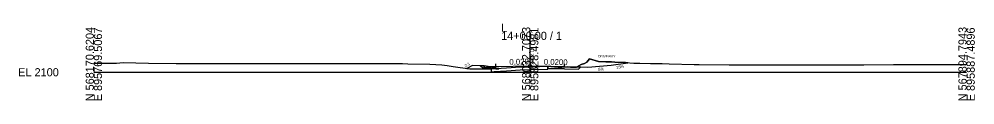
# Model space of a CAD drawing. Extents: x -26 to 1603, y -10 to 13527.
# Drawn here: x -25.7 to 302.8, y 1490.3 to 1516.7 of the extents above; entities that cross this region are included whole.
import ezdxf

# ---------------------------------------------------------------- set-up
doc = ezdxf.new("R2010")
doc.units = 0
for name, color, linetype in [('Default', 7, 'Continuous'), ('Exist XS Center Line Elevation Label', 7, 'Continuous'), ('Exist XS Ground Line', 7, 'Continuous'), ('Old_Level_61', 7, 'Continuous'), ('Old_Level_63', 7, 'Continuous'), ('Prop XS Ditch Slope Text', 7, 'Continuous'), ('Prop XS Ditch Standard Text', 7, 'Continuous'), ('Prop XS Earthwork Shape', 7, 'Continuous'), ('Prop XS EOT Tick Mark', 7, 'Continuous'), ('Prop XS Finish Grade', 7, 'Continuous'), ('Prop XS Finish Grade Earthwork', 7, 'Continuous'), ('Prop XS Finish Grade Paved Shoulder', 7, 'Continuous'), ('Prop XS Finish Grade Pavement', 7, 'Continuous'), ('Prop XS Subgrade Earthwork', 7, 'Continuous'), ('Prop XSC Text', 7, 'Continuous'), ('Typical Curb CELL', 7, 'Continuous')]:
    doc.layers.add(name, color=color, linetype=linetype)

msp = doc.modelspace()

# ---------------------------------------------------------------- linework, layer by layer
at = {"layer": 'Exist XS Ground Line'}
for p, q in [((0, 1503.13), (5.22, 1503.15)), ((5.22, 1503.15), (7.79, 1503.15)), ((7.79, 1503.15), (10.02, 1503.3)), ((10.02, 1503.3), (18.81, 1503.15)), ((18.81, 1503.15), (28.31, 1503.01)), ((28.31, 1503.01), (29.99, 1503.01)), ((29.99, 1503.01), (33.53, 1503)), ((33.53, 1503), (42.94, 1502.99)), ((42.94, 1502.99), (55.35, 1502.98)), ((55.35, 1502.98), (55.86, 1502.98)), ((55.86, 1502.98), (56.74, 1502.99)), ((56.74, 1502.99), (58.95, 1503)), ((58.95, 1503), (68.24, 1503.06)), ((68.24, 1503.06), (69.74, 1503.06)), ((69.74, 1503.06), (76.49, 1503)), ((76.49, 1503), (78.47, 1503)), ((78.47, 1503), (92.05, 1503.06)), ((92.05, 1503.06), (94.64, 1503.04)), ((94.64, 1503.04), (97.81, 1503.04)), ((97.81, 1503.04), (106.12, 1502.97)), ((106.12, 1502.97), (107.94, 1502.9)), ((107.94, 1502.9), (115.47, 1502.82)), ((115.47, 1502.82), (119.56, 1502.55)), ((119.56, 1502.55), (121.46, 1502.32)), ((121.46, 1502.32), (123.54, 1501.98)), ((123.54, 1501.98), (129.29, 1501.17)), ((136.4, 1501.17), (141.8, 1501.47)), ((141.8, 1501.47), (146.53, 1501.81)), ((146.53, 1501.81), (150, 1501.91)), ((150, 1501.91), (150.33, 1501.92)), ((150.33, 1501.92), (156.01, 1502.05)), ((156.01, 1502.05), (157.06, 1501.93)), ((157.06, 1501.93), (159.61, 1501.8)), ((159.61, 1501.8), (160.81, 1501.79)), ((160.81, 1501.79), (162.95, 1501.88)), ((162.95, 1501.88), (163.87, 1501.71)), ((163.87, 1501.71), (165.9, 1501.76)), ((165.9, 1501.76), (167.45, 1502.7)), ((167.45, 1502.7), (168.69, 1502.97)), ((168.69, 1502.97), (169.46, 1503.46)), ((169.46, 1503.46), (170.4, 1504.65)), ((170.4, 1504.65), (173.44, 1503.74)), ((173.44, 1503.74), (175.93, 1503.53)), ((175.93, 1503.53), (177.94, 1503.53)), ((177.94, 1503.53), (179.03, 1503.52)), ((179.03, 1503.52), (182.72, 1503.33)), ((182.72, 1503.33), (185.65, 1503.17)), ((185.65, 1503.17), (187.65, 1503.12)), ((187.65, 1503.12), (191.36, 1503)), ((191.36, 1503), (195.3, 1502.97)), ((195.3, 1502.97), (197.7, 1502.92)), ((197.7, 1502.92), (206.39, 1502.67)), ((206.39, 1502.67), (208.01, 1502.67)), ((208.01, 1502.67), (218.34, 1502.6)), ((218.34, 1502.6), (221.49, 1502.6)), ((221.49, 1502.6), (236.26, 1502.55)), ((236.26, 1502.55), (244.93, 1502.52)), ((244.93, 1502.52), (246.38, 1502.52)), ((246.38, 1502.52), (247.51, 1502.52)), ((247.51, 1502.52), (264.67, 1502.52)), ((264.67, 1502.52), (274.9, 1502.65)), ((274.9, 1502.65), (277.44, 1502.69)), ((277.44, 1502.69), (281.52, 1502.68)), ((281.52, 1502.68), (294.15, 1502.64)), ((294.15, 1502.64), (300, 1502.67)), ((129.29, 1501.17), (131.96, 1501.17)), ((131.96, 1501.17), (136.4, 1501.17))]:
    msp.add_line(p, q, dxfattribs=at)
at = {"layer": 'Old_Level_61'}
for p, q in [((156.05, 1501.05), (156.05, 1502.05)), ((136.54, 1501.18), (136.54, 1500.18)), ((136.54, 1500.18), (137.55, 1500.23)), ((137.55, 1500.23), (141.8, 1500.47)), ((141.8, 1500.47), (146.53, 1500.81)), ((146.53, 1500.81), (150, 1500.91)), ((150, 1500.91), (150.33, 1500.92)), ((150.33, 1500.92), (156.01, 1501.05)), ((156.01, 1501.05), (156.05, 1501.05))]:
    msp.add_line(p, q, dxfattribs=at)
at = {"layer": 'Old_Level_63'}
for p, q in [((150, 1500), (150, 1513.95)), ((0, 1500), (150, 1500)), ((150, 1500), (300, 1500))]:
    msp.add_line(p, q, dxfattribs=at)
at = {"layer": 'Prop XS Earthwork Shape'}
for points in [[(133.7, 1501.36), (132.83, 1502.23), (130.2, 1502.28), (128.26, 1501.31), (129.29, 1501.17), (131.96, 1501.17), (136.4, 1501.17), (138.2, 1501.27), (138.2, 1501.37), (134.2, 1501.37)], [(161.8, 1501.16), (166.63, 1501.07), (167.41, 1501.84), (169.8, 1501.79), (177.8, 1502.43), (183.49, 1503.29), (182.72, 1503.33), (179.03, 1503.52), (177.94, 1503.53), (175.93, 1503.53), (173.44, 1503.74), (170.4, 1504.65), (169.46, 1503.46), (168.69, 1502.97), (167.45, 1502.7), (165.9, 1501.76), (163.87, 1501.71), (162.95, 1501.88), (160.81, 1501.79), (159.61, 1501.8), (157.06, 1501.93), (156.05, 1502.05), (156.05, 1501.28)], [(138.2, 1501.16), (139.2, 1501.18), (139.2, 1501.32), (138.2, 1501.27)]]:
    msp.add_lwpolyline(points, close=True, dxfattribs=at)
at = {"layer": 'Prop XS EOT Tick Mark'}
for p, q in [((138.2, 1501.95), (138.2, 1502.95)), ((161.8, 1501.95), (161.8, 1502.95))]:
    msp.add_line(p, q, dxfattribs=at)
at = {"layer": 'Prop XS Finish Grade'}
for p, q in [((134.2, 1502.2), (132.83, 1502.23)), ((165.82, 1501.87), (167.41, 1501.84))]:
    msp.add_line(p, q, dxfattribs=at)
at = {"layer": 'Prop XS Finish Grade Earthwork'}
for p, q in [((130.2, 1502.28), (128.26, 1501.31)), ((132.83, 1502.23), (130.2, 1502.28)), ((167.41, 1501.84), (169.8, 1501.79)), ((169.8, 1501.79), (177.8, 1502.43)), ((177.8, 1502.43), (183.49, 1503.29))]:
    msp.add_line(p, q, dxfattribs=at)
at = {"layer": 'Prop XS Finish Grade Paved Shoulder'}
msp.add_line((161.8, 1501.95), (165.82, 1501.87), dxfattribs=at)
at = {"layer": 'Prop XS Finish Grade Pavement'}
for p, q in [((138.2, 1501.95), (150, 1502.19)), ((150, 1502.19), (161.8, 1501.95))]:
    msp.add_line(p, q, dxfattribs=at)
at = {"layer": 'Prop XS Subgrade Earthwork'}
for p, q in [((133.7, 1501.36), (132.83, 1502.23)), ((156.05, 1501.28), (156.05, 1502.05)), ((166.63, 1501.07), (167.41, 1501.84)), ((133.7, 1501.36), (134.2, 1501.37)), ((134.2, 1501.37), (138.2, 1501.37)), ((138.2, 1501.16), (138.2, 1501.37)), ((138.2, 1501.16), (139.2, 1501.18)), ((139.2, 1501.18), (139.2, 1501.32)), ((161.8, 1501.16), (156.05, 1501.28)), ((161.8, 1501.16), (166.63, 1501.07))]:
    msp.add_line(p, q, dxfattribs=at)
at = {"layer": 'Typical Curb CELL'}
for p, q in [((134.2, 1501.37), (134.2, 1502.2)), ((136.2, 1501.87), (134.2, 1502.2)), ((134.24, 1501.83), (134.39, 1501.87)), ((134.37, 1501.78), (134.24, 1501.83)), ((134.39, 1501.87), (134.37, 1501.78)), ((134.91, 1501.74), (134.8, 1501.67)), ((134.8, 1501.67), (134.97, 1501.63)), ((134.97, 1501.63), (134.91, 1501.74)), ((135.65, 1501.8), (135.61, 1501.69)), ((135.61, 1501.69), (135.73, 1501.68)), ((135.73, 1501.68), (135.65, 1501.8)), ((136.16, 1501.74), (136.05, 1501.67)), ((136.05, 1501.67), (136.22, 1501.63)), ((136.22, 1501.63), (136.16, 1501.74)), ((138.2, 1501.95), (136.2, 1501.87)), ((136.9, 1501.8), (136.86, 1501.69)), ((136.86, 1501.69), (136.98, 1501.68)), ((136.98, 1501.68), (136.9, 1501.8)), ((137.61, 1501.6), (137.51, 1501.52)), ((137.51, 1501.52), (137.67, 1501.48)), ((137.67, 1501.48), (137.61, 1501.6)), ((137.94, 1501.84), (137.91, 1501.73)), ((137.91, 1501.73), (138.03, 1501.72)), ((138.03, 1501.72), (137.94, 1501.84)), ((138.2, 1501.37), (138.2, 1501.95)), ((134.2, 1501.37), (138.2, 1501.37))]:
    msp.add_line(p, q, dxfattribs=at)
for centre in [(134.27, 1501.91), (134.36, 1501.64), (134.38, 1502.08), (134.45, 1501.53), (134.48, 1501.69), (134.58, 1502.06), (134.74, 1501.72), (134.76, 1501.67), (134.93, 1501.58), (134.95, 1501.98), (134.96, 1501.68), (135.15, 1501.46), (135.16, 1501.64), (135.2, 1501.76), (135.31, 1501.92), (135.33, 1501.73), (135.36, 1501.6), (135.42, 1501.64), (135.47, 1501.51), (135.61, 1501.64), (135.73, 1501.69), (135.77, 1501.83), (135.83, 1501.68), (135.83, 1501.48), (135.92, 1501.63), (135.98, 1501.78), (135.99, 1501.72), (136.01, 1501.67), (136.18, 1501.57), (136.21, 1501.68), (136.29, 1501.49), (136.41, 1501.64), (136.45, 1501.76), (136.5, 1501.73), (136.52, 1501.45), (136.58, 1501.73), (136.61, 1501.6), (136.67, 1501.64), (136.73, 1501.82), (136.84, 1501.46), (137.09, 1501.89), (137.13, 1501.77), (137.33, 1501.54), (137.48, 1501.81), (137.7, 1501.82), (137.77, 1501.59), (137.94, 1501.45), (138.06, 1501.61), (138.1, 1501.85)]:
    msp.add_circle(centre, 0.00802, dxfattribs=at)

# ---------------------------------------------------------------- texts
at = {"layer": 'Default'}
for rotation, p in [(1.1458, (142.84, 1502.55)), (358.8542, (154.64, 1502.6))]:
    msp.add_text('0.0200', height=2, rotation=rotation, dxfattribs=at).set_placement(p)
at = {"layer": 'Exist XS Center Line Elevation Label'}
msp.add_text('2101.91', height=1, rotation=90, dxfattribs=at).set_placement((150.5, 1494.95))
at = {"layer": 'Old_Level_63'}
for s, p in [('N 568170.6204', (0, 1490)), ('E 895769.5067', (2.8, 1490)), ('N 568032.7073', (150, 1490)), ('E 895828.4981', (152.8, 1490)), ('N 567894.7943', (300, 1490)), ('E 895887.4896', (302.8, 1490))]:
    msp.add_text(s, height=2.8, rotation=90, dxfattribs=at).set_placement(p)
for s, p in [('L', (140, 1513.95)), ('14+00.00 / 1', (140, 1511.15)), ('EL 2100', (-26, 1498.6))]:
    msp.add_text(s, height=2.8, dxfattribs=at).set_placement(p)
at = {"layer": 'Prop XS Ditch Slope Text'}
msp.add_text('2:1', height=1, rotation=32.2598, dxfattribs=at).set_placement((127.78, 1501.62))
at = {"layer": 'Prop XS Ditch Standard Text'}
msp.add_text('DRIVEWAY', height=0.8, dxfattribs=at).set_placement((173.34, 1505.1))
for s, rotation, p in [('8%', 4.5739, (173.39, 1500.5)), ('15%', 9.8514, (179.64, 1501.13))]:
    msp.add_text(s, height=1, rotation=rotation, dxfattribs=at).set_placement(p)
at = {"layer": 'Prop XSC Text'}
msp.add_text(' 2102.19', height=1.2, rotation=90, dxfattribs=at).set_placement((151.2, 1502.19))

doc.saveas('drawing.dxf')
